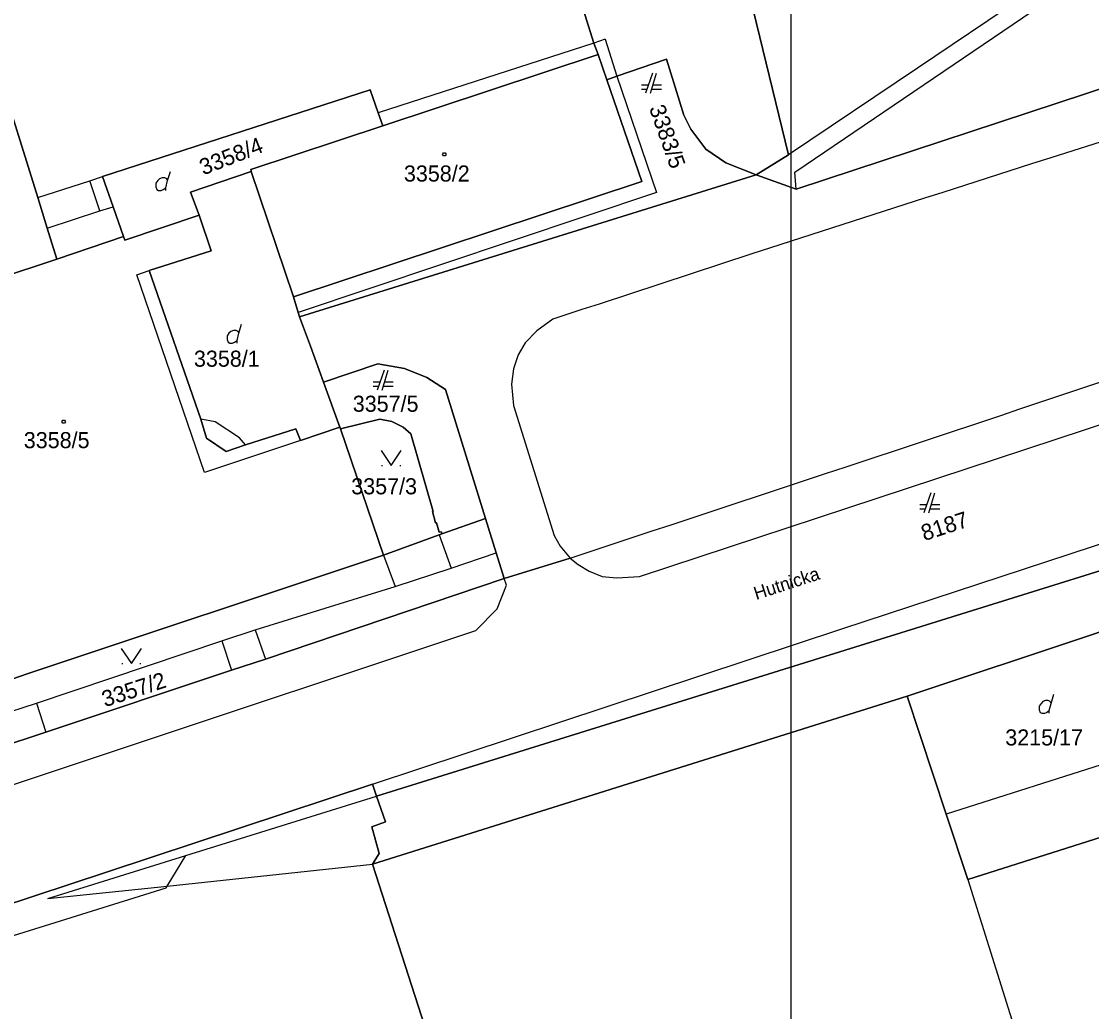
# Model space of a CAD drawing. Extents: x -263587 to -261993, y -1238795 to -1236748.
# Drawn here: x -262771.6 to -262665.1, y -1238657.9 to -1238559.4 of the extents above; entities that cross this region are included whole.
import ezdxf

# ---------------------------------------------------------------- set-up
doc = ezdxf.new("R2010")
doc.units = 0
doc.layers.add('Vrstva 1', color=7, linetype='Continuous')
doc.layers.add('Vrstva 51', color=7, linetype='Continuous')

msp = doc.modelspace()

# ---------------------------------------------------------------- linework, layer by layer
at = {"layer": 'Vrstva 1'}
for p, q in [((-262714.62, -1238561.6), (-262726.98, -1238521.95)), ((-262726.98, -1238521.95), (-262714.62, -1238561.6)), ((-262699.75, -1238554.24), (-262695.25, -1238572.71)), ((-262695.25, -1238572.71), (-262699.75, -1238554.24)), ((-262667.92, -1238554.3), (-262682.42, -1238564.07)), ((-262694.61, -1238574.44), (-262667.25, -1238555.85)), ((-262714.62, -1238561.6), (-262736.06, -1238568.51)), ((-262713.49, -1238561.21), (-262714.62, -1238561.6)), ((-262714.19, -1238562.73), (-262714.62, -1238561.6)), ((-262714.62, -1238561.6), (-262714.19, -1238562.73)), ((-262713.49, -1238561.21), (-262712.33, -1238564.89)), ((-262769.95, -1238576.95), (-262774.47, -1238562.46)), ((-262774.47, -1238562.46), (-262769.95, -1238576.95)), ((-262735.62, -1238569.81), (-262714.19, -1238562.73)), ((-262714.19, -1238562.73), (-262735.62, -1238569.81)), ((-262713.33, -1238565.23), (-262714.19, -1238562.73)), ((-262714.19, -1238562.73), (-262713.33, -1238565.23)), ((-262712.33, -1238564.89), (-262707.39, -1238563.2)), ((-262707.39, -1238563.2), (-262712.33, -1238564.89)), ((-262707.39, -1238563.2), (-262705.65, -1238568.75)), ((-262705.65, -1238568.75), (-262707.39, -1238563.2)), ((-262682.42, -1238564.07), (-262695.25, -1238572.71)), ((-262713.33, -1238565.23), (-262712.33, -1238564.89)), ((-262712.33, -1238564.89), (-262713.33, -1238565.23)), ((-262712.33, -1238564.89), (-262708.37, -1238576.46)), ((-262708.79, -1238564.58), (-262709.49, -1238566.58)), ((-262708.99, -1238566.58), (-262708.39, -1238564.58)), ((-262694.48, -1238576.11), (-262658.28, -1238564.19)), ((-262658.28, -1238564.19), (-262694.48, -1238576.11)), ((-262736.87, -1238566.23), (-262763.5, -1238574.85)), ((-262763.5, -1238574.85), (-262736.87, -1238566.23)), ((-262736.06, -1238568.51), (-262736.87, -1238566.23)), ((-262736.87, -1238566.23), (-262736.06, -1238568.51)), ((-262709.83, -1238575.35), (-262713.33, -1238565.23)), ((-262713.33, -1238565.23), (-262709.83, -1238575.35)), ((-262709.21, -1238565.78), (-262709.89, -1238565.78)), ((-262709.89, -1238566.18), (-262709.35, -1238566.18)), ((-262708.87, -1238566.18), (-262707.89, -1238566.18)), ((-262707.89, -1238565.78), (-262708.75, -1238565.78)), ((-262653.77, -1238568.13), (-262669.15, -1238572.99)), ((-262735.62, -1238569.81), (-262736.06, -1238568.51)), ((-262736.06, -1238568.51), (-262735.62, -1238569.81)), ((-262705.65, -1238568.75), (-262704.97, -1238570.14)), ((-262704.97, -1238570.14), (-262705.65, -1238568.75)), ((-262748.76, -1238574.16), (-262735.62, -1238569.81)), ((-262735.62, -1238569.81), (-262748.76, -1238574.16)), ((-262704.97, -1238570.14), (-262703.47, -1238572.14)), ((-262703.47, -1238572.14), (-262704.97, -1238570.14)), ((-262703.47, -1238572.14), (-262701.48, -1238573.5)), ((-262701.48, -1238573.5), (-262703.47, -1238572.14)), ((-262701.48, -1238573.5), (-262698.48, -1238574.68)), ((-262698.48, -1238574.68), (-262701.48, -1238573.5)), ((-262695.25, -1238572.71), (-262698.48, -1238574.68)), ((-262698.48, -1238574.68), (-262695.25, -1238572.71)), ((-262671.07, -1238573.61), (-262679.9, -1238576.44)), ((-262669.15, -1238572.99), (-262671.07, -1238573.61)), ((-262757.02, -1238575.26), (-262756.75, -1238574.36)), ((-262748.7, -1238574.36), (-262754.73, -1238576.41)), ((-262754.73, -1238576.41), (-262748.7, -1238574.36)), ((-262748.72, -1238574.29), (-262748.76, -1238574.16)), ((-262748.76, -1238574.16), (-262748.72, -1238574.29)), ((-262748.7, -1238574.36), (-262748.72, -1238574.29)), ((-262748.72, -1238574.29), (-262748.7, -1238574.36)), ((-262744.5, -1238586.83), (-262748.7, -1238574.36)), ((-262748.7, -1238574.36), (-262744.5, -1238586.83)), ((-262698.48, -1238574.68), (-262743.89, -1238588.82)), ((-262743.89, -1238588.82), (-262698.48, -1238574.68)), ((-262698.48, -1238574.68), (-262694.48, -1238576.11)), ((-262694.48, -1238576.11), (-262698.48, -1238574.68)), ((-262694.48, -1238576.11), (-262694.61, -1238574.44)), ((-262769.95, -1238576.95), (-262764.76, -1238575.28)), ((-262764.76, -1238575.28), (-262763.5, -1238574.85)), ((-262763.76, -1238578.28), (-262764.76, -1238575.28)), ((-262763.5, -1238574.85), (-262762.45, -1238577.87)), ((-262762.45, -1238577.87), (-262763.5, -1238574.85)), ((-262744.5, -1238586.83), (-262709.83, -1238575.35)), ((-262709.83, -1238575.35), (-262744.5, -1238586.83)), ((-262754.73, -1238576.41), (-262753.89, -1238578.72)), ((-262753.89, -1238578.72), (-262754.73, -1238576.41)), ((-262708.37, -1238576.46), (-262744.02, -1238588.38)), ((-262679.9, -1238576.44), (-262681.72, -1238577.01)), ((-262769, -1238579.99), (-262769.95, -1238576.95)), ((-262769.95, -1238576.95), (-262769, -1238579.99)), ((-262763.76, -1238578.28), (-262762.45, -1238577.87)), ((-262762.45, -1238577.87), (-262761.4, -1238580.84)), ((-262761.4, -1238580.84), (-262762.45, -1238577.87)), ((-262681.72, -1238577.01), (-262697.05, -1238581.96)), ((-262769, -1238579.99), (-262763.76, -1238578.28)), ((-262761.27, -1238581.18), (-262753.89, -1238578.72)), ((-262753.89, -1238578.72), (-262761.27, -1238581.18)), ((-262753.89, -1238578.72), (-262752.69, -1238582.25)), ((-262752.69, -1238582.25), (-262753.89, -1238578.72)), ((-262768.04, -1238583.09), (-262769, -1238579.99)), ((-262769, -1238579.99), (-262768.04, -1238583.09)), ((-262761.4, -1238580.84), (-262768.04, -1238583.09)), ((-262768.04, -1238583.09), (-262761.4, -1238580.84)), ((-262761.4, -1238580.84), (-262761.27, -1238581.18)), ((-262761.27, -1238581.18), (-262761.4, -1238580.84)), ((-262752.69, -1238582.25), (-262758.86, -1238584.22)), ((-262758.86, -1238584.22), (-262752.69, -1238582.25)), ((-262697.05, -1238581.96), (-262698.91, -1238582.55)), ((-262768.04, -1238583.09), (-262785.54, -1238588.81)), ((-262785.54, -1238588.81), (-262768.04, -1238583.09)), ((-262698.91, -1238582.55), (-262714.09, -1238587.54)), ((-262760.08, -1238584.65), (-262758.86, -1238584.22)), ((-262758.86, -1238584.22), (-262753.73, -1238599.01)), ((-262753.73, -1238599.01), (-262758.86, -1238584.22)), ((-262753.36, -1238604.31), (-262760.08, -1238584.65)), ((-262744.02, -1238588.38), (-262744.5, -1238586.83)), ((-262744.5, -1238586.83), (-262744.02, -1238588.38)), ((-262714.09, -1238587.54), (-262715.81, -1238588.1)), ((-262743.89, -1238588.82), (-262744.02, -1238588.38)), ((-262744.02, -1238588.38), (-262743.89, -1238588.82)), ((-262715.81, -1238588.1), (-262718.71, -1238589.04)), ((-262749.93, -1238590.44), (-262749.66, -1238589.54)), ((-262743.89, -1238588.82), (-262742.82, -1238591.72)), ((-262742.82, -1238591.72), (-262743.89, -1238588.82)), ((-262718.71, -1238589.04), (-262720.28, -1238590.21)), ((-262720.28, -1238590.21), (-262721.46, -1238591.4)), ((-262742.82, -1238591.72), (-262741.51, -1238595.33)), ((-262741.51, -1238595.33), (-262742.82, -1238591.72)), ((-262721.46, -1238591.4), (-262722.16, -1238592.6)), ((-262722.16, -1238592.6), (-262722.6, -1238593.98)), ((-262710.08, -1238614.66), (-262641.8, -1238592.15)), ((-262736.1, -1238593.48), (-262741.51, -1238595.33)), ((-262741.51, -1238595.33), (-262736.1, -1238593.48)), ((-262733.44, -1238593.97), (-262736.1, -1238593.48)), ((-262736.1, -1238593.48), (-262733.44, -1238593.97)), ((-262671.41, -1238616.29), (-262597.4, -1238593.4)), ((-262597.4, -1238593.4), (-262671.41, -1238616.29)), ((-262735.48, -1238594.12), (-262736.18, -1238596.12)), ((-262735.68, -1238596.12), (-262735.08, -1238594.12)), ((-262731.24, -1238594.86), (-262733.44, -1238593.97)), ((-262733.44, -1238593.97), (-262731.24, -1238594.86)), ((-262729.39, -1238596.03), (-262731.24, -1238594.86)), ((-262731.24, -1238594.86), (-262729.39, -1238596.03)), ((-262722.6, -1238593.98), (-262722.81, -1238595.51)), ((-262741.51, -1238595.33), (-262739.88, -1238599.8)), ((-262739.88, -1238599.8), (-262741.51, -1238595.33)), ((-262735.9, -1238595.32), (-262736.58, -1238595.32)), ((-262736.58, -1238595.72), (-262736.04, -1238595.72)), ((-262735.56, -1238595.72), (-262734.58, -1238595.72)), ((-262734.58, -1238595.32), (-262735.44, -1238595.32)), ((-262725.39, -1238608.86), (-262729.39, -1238596.03)), ((-262729.39, -1238596.03), (-262725.39, -1238608.86)), ((-262722.81, -1238595.51), (-262722.61, -1238597.62)), ((-262672.23, -1238597.97), (-262663.77, -1238595.15)), ((-262722.61, -1238597.62), (-262718.58, -1238610.56)), ((-262674.14, -1238598.63), (-262672.23, -1238597.97)), ((-262753.73, -1238599.01), (-262753.15, -1238600.87)), ((-262753.15, -1238600.87), (-262753.73, -1238599.01)), ((-262752.3, -1238599.25), (-262753.73, -1238599.01)), ((-262749.88, -1238600.86), (-262752.3, -1238599.25)), ((-262735.9, -1238598.99), (-262739.82, -1238599.96)), ((-262739.82, -1238599.96), (-262735.9, -1238598.99)), ((-262734.71, -1238599.22), (-262735.9, -1238598.99)), ((-262735.9, -1238598.99), (-262734.71, -1238599.22)), ((-262733.58, -1238599.79), (-262734.71, -1238599.22)), ((-262734.71, -1238599.22), (-262733.58, -1238599.79)), ((-262689.96, -1238619.86), (-262624.16, -1238598.23)), ((-262689.5, -1238603.73), (-262674.14, -1238598.63)), ((-262749.26, -1238601.54), (-262744.26, -1238599.95)), ((-262744.26, -1238599.95), (-262749.26, -1238601.54)), ((-262744.26, -1238599.95), (-262743.79, -1238601.11)), ((-262743.79, -1238601.11), (-262744.26, -1238599.95)), ((-262743.79, -1238601.11), (-262739.88, -1238599.8)), ((-262739.88, -1238599.8), (-262743.79, -1238601.11)), ((-262739.88, -1238599.8), (-262739.82, -1238599.96)), ((-262739.82, -1238599.96), (-262739.88, -1238599.8)), ((-262739.82, -1238599.96), (-262735.54, -1238612.51)), ((-262735.54, -1238612.51), (-262739.82, -1238599.96)), ((-262732.83, -1238600.47), (-262733.58, -1238599.79)), ((-262733.58, -1238599.79), (-262732.83, -1238600.47)), ((-262743.79, -1238601.11), (-262753.36, -1238604.31)), ((-262753.15, -1238600.87), (-262751.19, -1238602.22)), ((-262751.19, -1238602.22), (-262753.15, -1238600.87)), ((-262749.26, -1238601.54), (-262749.88, -1238600.86)), ((-262730.61, -1238608.17), (-262732.83, -1238600.47)), ((-262732.83, -1238600.47), (-262730.61, -1238608.17)), ((-262751.19, -1238602.22), (-262749.26, -1238601.54)), ((-262749.26, -1238601.54), (-262751.19, -1238602.22)), ((-262735.73, -1238603.6), (-262735.63, -1238603.6)), ((-262733.93, -1238603.6), (-262733.83, -1238603.6)), ((-262706.81, -1238609.46), (-262691.58, -1238604.4)), ((-262691.58, -1238604.4), (-262689.5, -1238603.73)), ((-262681.09, -1238606.31), (-262681.79, -1238608.31)), ((-262681.29, -1238608.31), (-262680.69, -1238606.31)), ((-262681.51, -1238607.51), (-262682.19, -1238607.51)), ((-262680.19, -1238607.51), (-262681.05, -1238607.51)), ((-262730.67, -1238608.18), (-262730.61, -1238608.17)), ((-262730.61, -1238608.17), (-262730.67, -1238608.18)), ((-262730.37, -1238609.32), (-262730.67, -1238608.18)), ((-262730.67, -1238608.18), (-262730.37, -1238609.32)), ((-262729.73, -1238610.39), (-262725.39, -1238608.86)), ((-262725.39, -1238608.86), (-262729.73, -1238610.39)), ((-262725.39, -1238608.86), (-262724.33, -1238612.29)), ((-262724.33, -1238612.29), (-262725.39, -1238608.86)), ((-262682.19, -1238607.91), (-262681.65, -1238607.91)), ((-262681.17, -1238607.91), (-262680.19, -1238607.91)), ((-262730.26, -1238609.29), (-262730.37, -1238609.32)), ((-262730.37, -1238609.32), (-262730.26, -1238609.29)), ((-262730, -1238610.24), (-262730.26, -1238609.29)), ((-262730.26, -1238609.29), (-262730, -1238610.24)), ((-262708.93, -1238610.13), (-262706.81, -1238609.46)), ((-262735.54, -1238612.51), (-262730.02, -1238610.49)), ((-262730.02, -1238610.49), (-262735.54, -1238612.51)), ((-262730.02, -1238610.49), (-262729.73, -1238610.39)), ((-262729.73, -1238610.39), (-262730.02, -1238610.49)), ((-262730.02, -1238610.49), (-262728.82, -1238613.81)), ((-262729.79, -1238610.2), (-262730, -1238610.24)), ((-262730, -1238610.24), (-262729.79, -1238610.2)), ((-262729.73, -1238610.39), (-262729.79, -1238610.2)), ((-262729.79, -1238610.2), (-262729.73, -1238610.39)), ((-262718.58, -1238610.56), (-262717.96, -1238611.63)), ((-262716.97, -1238612.82), (-262708.93, -1238610.13)), ((-262717.96, -1238611.63), (-262716.97, -1238612.82)), ((-262735.54, -1238612.51), (-262771.01, -1238624.31)), ((-262771.01, -1238624.31), (-262735.54, -1238612.51)), ((-262735.54, -1238612.51), (-262734.4, -1238615.64)), ((-262728.82, -1238613.81), (-262724.33, -1238612.29)), ((-262724.33, -1238612.29), (-262723.53, -1238614.84)), ((-262723.53, -1238614.84), (-262724.33, -1238612.29)), ((-262723.53, -1238614.84), (-262716.97, -1238612.82)), ((-262716.97, -1238612.82), (-262723.53, -1238614.84)), ((-262716.97, -1238612.82), (-262716.19, -1238613.45)), ((-262734.4, -1238615.64), (-262728.82, -1238613.81)), ((-262716.19, -1238613.45), (-262715.09, -1238614.1)), ((-262715.09, -1238614.1), (-262713.78, -1238614.64)), ((-262747.3, -1238622.86), (-262723.53, -1238614.84)), ((-262723.53, -1238614.84), (-262747.3, -1238622.86)), ((-262723.32, -1238615.51), (-262723.53, -1238614.84)), ((-262713.78, -1238614.64), (-262712.32, -1238614.79)), ((-262712.32, -1238614.79), (-262710.08, -1238614.66)), ((-262748.3, -1238619.96), (-262734.4, -1238615.64)), ((-262736.24, -1238636.49), (-262671.41, -1238616.29)), ((-262671.41, -1238616.29), (-262736.24, -1238636.49)), ((-262724.23, -1238617.87), (-262723.32, -1238615.51)), ((-262665.21, -1238620.49), (-262655.82, -1238617.26)), ((-262655.82, -1238617.26), (-262665.21, -1238620.49)), ((-262726.35, -1238620), (-262724.23, -1238617.87)), ((-262762.82, -1238632.15), (-262726.35, -1238620)), ((-262751.63, -1238621.05), (-262748.3, -1238619.96)), ((-262748.3, -1238619.96), (-262747.3, -1238622.86)), ((-262736.65, -1238635.31), (-262689.96, -1238619.86)), ((-262683.43, -1238626.55), (-262665.21, -1238620.49)), ((-262665.21, -1238620.49), (-262683.43, -1238626.55)), ((-262770.06, -1238627.24), (-262751.63, -1238621.05)), ((-262751.63, -1238621.05), (-262750.66, -1238623.97)), ((-262761.58, -1238623.3), (-262761.48, -1238623.3)), ((-262759.78, -1238623.3), (-262759.68, -1238623.3)), ((-262750.66, -1238623.97), (-262747.3, -1238622.86)), ((-262747.3, -1238622.86), (-262750.66, -1238623.97)), ((-262771.01, -1238624.31), (-262775.73, -1238625.98)), ((-262775.73, -1238625.98), (-262771.01, -1238624.31)), ((-262769.15, -1238630.12), (-262750.66, -1238623.97)), ((-262750.66, -1238623.97), (-262769.15, -1238630.12)), ((-262736.63, -1238643.27), (-262683.43, -1238626.55)), ((-262683.43, -1238626.55), (-262736.63, -1238643.27)), ((-262679.56, -1238638.28), (-262683.43, -1238626.55)), ((-262683.43, -1238626.55), (-262679.56, -1238638.28)), ((-262669.13, -1238627.26), (-262668.86, -1238626.36)), ((-262775.04, -1238628.86), (-262770.06, -1238627.24)), ((-262770.06, -1238627.24), (-262769.15, -1238630.12)), ((-262774.15, -1238631.78), (-262769.15, -1238630.12)), ((-262769.15, -1238630.12), (-262774.15, -1238631.78)), ((-262651.94, -1238629.5), (-262679.56, -1238638.28)), ((-262802.2, -1238645.27), (-262762.82, -1238632.15)), ((-262762.99, -1238644.02), (-262736.65, -1238635.31)), ((-262736.65, -1238635.31), (-262762.99, -1238644.02)), ((-262736.65, -1238635.31), (-262736.24, -1238636.49)), ((-262736.24, -1238636.49), (-262736.65, -1238635.31)), ((-262755.22, -1238642.41), (-262736.24, -1238636.49)), ((-262735.34, -1238639.04), (-262736.24, -1238636.49)), ((-262736.24, -1238636.49), (-262735.34, -1238639.04)), ((-262649.98, -1238636.07), (-262677.4, -1238644.79)), ((-262677.4, -1238644.79), (-262649.98, -1238636.07)), ((-262677.4, -1238644.79), (-262679.56, -1238638.28)), ((-262679.56, -1238638.28), (-262677.4, -1238644.79)), ((-262736.71, -1238639.53), (-262735.34, -1238639.04)), ((-262735.34, -1238639.04), (-262736.71, -1238639.53)), ((-262735.99, -1238642.2), (-262736.71, -1238639.53)), ((-262736.71, -1238639.53), (-262735.99, -1238642.2)), ((-262768.93, -1238646.68), (-262755.22, -1238642.41)), ((-262757.07, -1238645.43), (-262755.22, -1238642.41)), ((-262736.63, -1238643.27), (-262735.99, -1238642.2)), ((-262735.99, -1238642.2), (-262736.63, -1238643.27)), ((-262757.07, -1238645.43), (-262736.63, -1238643.27)), ((-262714.42, -1238712.3), (-262736.63, -1238643.27)), ((-262736.63, -1238643.27), (-262714.42, -1238712.3)), ((-262791.59, -1238653.43), (-262762.99, -1238644.02)), ((-262762.99, -1238644.02), (-262791.59, -1238653.43)), ((-262677.4, -1238644.79), (-262672.32, -1238661.03)), ((-262787.91, -1238655.23), (-262757.18, -1238645.61)), ((-262768.93, -1238646.68), (-262757.07, -1238645.43)), ((-262757.18, -1238645.61), (-262757.07, -1238645.43))]:
    msp.add_line(p, q, dxfattribs=at)
for points in [[(-262729.41, -1238572.51), (-262729.32, -1238572.66), (-262729.41, -1238572.81), (-262729.59, -1238572.81), (-262729.68, -1238572.66), (-262729.59, -1238572.51)], [(-262767.27, -1238599.1), (-262767.18, -1238599.25), (-262767.27, -1238599.4), (-262767.45, -1238599.4), (-262767.54, -1238599.25), (-262767.45, -1238599.1)]]:
    msp.add_lwpolyline(points, close=True, dxfattribs=at)
for points in [[(-262757.2, -1238576.25), (-262757.2, -1238575.98), (-262757.02, -1238575.26), (-262757.11, -1238575.08), (-262757.29, -1238574.99), (-262757.56, -1238574.99), (-262757.83, -1238575.08), (-262758.01, -1238575.26), (-262758.19, -1238575.53), (-262758.19, -1238575.89), (-262758.1, -1238576.16), (-262757.92, -1238576.25), (-262757.65, -1238576.25), (-262757.47, -1238576.16), (-262757.2, -1238575.98)], [(-262750.11, -1238591.43), (-262750.11, -1238591.16), (-262749.93, -1238590.44), (-262750.02, -1238590.26), (-262750.2, -1238590.17), (-262750.47, -1238590.17), (-262750.74, -1238590.26), (-262750.92, -1238590.44), (-262751.1, -1238590.71), (-262751.1, -1238591.07), (-262751.01, -1238591.34), (-262750.83, -1238591.43), (-262750.56, -1238591.43), (-262750.38, -1238591.34), (-262750.11, -1238591.16)], [(-262735.78, -1238602.1), (-262734.78, -1238603.6), (-262733.78, -1238602.1)], [(-262761.63, -1238621.8), (-262760.63, -1238623.3), (-262759.63, -1238621.8)], [(-262669.31, -1238628.25), (-262669.31, -1238627.98), (-262669.13, -1238627.26), (-262669.22, -1238627.08), (-262669.4, -1238626.99), (-262669.67, -1238626.99), (-262669.94, -1238627.08), (-262670.12, -1238627.26), (-262670.3, -1238627.53), (-262670.3, -1238627.89), (-262670.21, -1238628.16), (-262670.03, -1238628.25), (-262669.76, -1238628.25), (-262669.58, -1238628.16), (-262669.31, -1238627.98)]]:
    msp.add_lwpolyline(points, dxfattribs=at)
at = {"layer": 'Vrstva 51'}
msp.add_lwpolyline([(-262992.03, -1237088.09), (-262695.03, -1237088.09), (-262695.03, -1238768.09), (-262992.03, -1238768.09)], close=True, dxfattribs=at)

# ---------------------------------------------------------------- texts
at = {"layer": 'Vrstva 1'}
for s, height, rotation, p in [('3383/5', 1.6, 289.51558, (-262709.142, -1238568.048)), ('3358/4', 1.6, 21.31403, (-262753.47, -1238574.756)), ('8187', 1.6, 17.99087, (-262681.745, -1238611.127)), ('Hutnicka', 1.3, 17.99087, (-262698.46, -1238616.986)), ('3357/2', 1.6, 17.99087, (-262763.258, -1238627.652))]:
    msp.add_text(s, height=height, rotation=rotation, dxfattribs=at).set_placement(p)
for s, p in [('3358/2', (-262733.513, -1238575.36)), ('3358/1', (-262754.404, -1238593.78)), ('3357/5', (-262738.603, -1238598.26)), ('3358/5', (-262771.333, -1238601.88)), ('3357/3', (-262738.753, -1238606.47)), ('3215/17', (-262673.684, -1238631.45))]:
    msp.add_text(s, height=1.6, dxfattribs=at).set_placement(p)

doc.saveas('drawing.dxf')
